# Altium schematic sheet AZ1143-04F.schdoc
size 127 x 101 mm
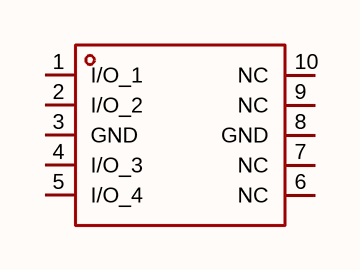
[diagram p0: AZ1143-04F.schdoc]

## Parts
U?  az1143-04f  [DFN-10_L2.5-W1.0-P0.50-BL-A]  (value not drawn)

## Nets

Not connected (* = marked no-connect by the designer): U? 1(I/O_1) 2(I/O_2) 3(GND) 4(I/O_3) 5(I/O_4) 6(NC) 7(NC) 8(GND) 9(NC) 10(NC)

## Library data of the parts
U? = az1143-04f: 反向截止电压(Vrwm):3.3V;钳位电压:15V;峰值脉冲电流(Ipp):4A@8/20us;击穿电压:3.6V;; Manufacturer: TECH PUBLIC(台舟); AddInBom: yes; ModelId: 5596653e199843b4b29af03f51901ce5; ModelTransform: 98.425,39.44874,0,0,0,0,0,0,0; Reverse Stand-Off Voltage (Vrwm): 3.3V; Clamping Voltage: 15V; Voltage - Breakdown: 3.6V; Reverse Leakage Current (Ir): 60nA; level of protection: IEC 61000-4-4；IEC 61000-4-5；IEC 61000-4-2; Junction Capacitance: 0.3pF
